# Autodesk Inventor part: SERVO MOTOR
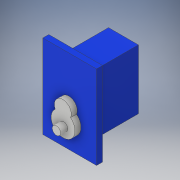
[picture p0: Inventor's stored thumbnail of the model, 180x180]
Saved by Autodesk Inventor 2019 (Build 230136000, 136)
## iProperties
Created: 2021-07
Part Number: SERVO MOTOR
Material: Generic
Document SubType Name: Modeling
Designer: Avinash
Density: 1 g/cm^3
Appearance: Default
Author: Avinash
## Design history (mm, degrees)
sketch "Sketch1"
  geometry: L1 (0, 0)-(-25, 0); L2 (-25, 0)-(-25, 50); L3 (-25, 50)-(0, 50); L4 (0, 50)-(0, 0)
  constraints: 8 end point, 2 parallel, 1 horizontal, 1 perpendicular
  dimensions: "d0" = 25 distance of L2.end L3.end; "d1" = 50 distance of L3.end L1.start
extrude "Extrusion1" new body sketch "Sketch1" distance "d2" = 40; taper "d3" = 0 deg
sketch "Sketch2"
  geometry: L1 (10, -10)-(-35, -10); L2 (-35, -10)-(-35, 60); L3 (-35, 60)-(10, 60); L4 (10, 60)-(10, -10); L5 (-25, 50)-(-25, 0) reference; L6 (0, 50)-(-25, 50) reference; L7 (-25, 0)-(0, 0) reference; L8 (0, 0)-(0, 50) reference
  constraints: 8 end point, 2 parallel, 1 horizontal, 1 perpendicular
  dimensions: "d4" = 10 distance between parallel lines of L2 L5; "d5" = 10 distance between parallel lines of L3 L6; "d6" = 10 distance between parallel lines of L7 L1; "d7" = 10 distance between parallel lines of L4 L8
extrude "Extrusion2" join sketch "Sketch2" distance "d8" = 5; taper "d9" = 0 deg
sketch "Sketch3"
  geometry: L1 (-25, 50)-(-25, 0) reference; A1 r 10 centre (-13.049, 11.056) between (-19.661, 18.558) and (-6.747, 18.821); A2 r 7.103 centre (-13.264, 21.647) between (-6.747, 18.821) and (-19.661, 18.558); 1 further point
  constraints: 4 point on circle, 2 centre point
  dimensions: "d10" = 20 diameter of A1
extrude "Extrusion3" join sketch "Sketch3" distance "d12" = 5; taper "d13" = 0 deg
sketch "Sketch4"
  geometry: C1 r 3.5 at (-12.599, 9.494); 1 further point
  constraints: 1 centre point
  dimensions: "d21" = 7 diameter of C1
extrude "Extrusion4" join sketch "Sketch4" distance "d14" = 6; taper "d15" = 0 deg
body "Solid1"
